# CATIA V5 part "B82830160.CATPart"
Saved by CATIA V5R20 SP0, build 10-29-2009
Part number: B82830160
Revision: 4
Definition: design
Nomenclature: B82830160
Source: made
Description: NOT SPECIFIED
Bounding box of the stored display mesh (mm): x -17.817 to 17.817, y -18 to 18, z 0 to 160
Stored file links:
  C:\Users\Raffaele\Desktop\3D X SITO CF\BOLEX\7-PILLAR REF 828\B82830160.CATPart
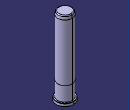
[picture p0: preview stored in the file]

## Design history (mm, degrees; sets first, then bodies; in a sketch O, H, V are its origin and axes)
Body1 "MANIFOLD_SOLID_BREP #450" (main body)
  Solid1: solid without history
